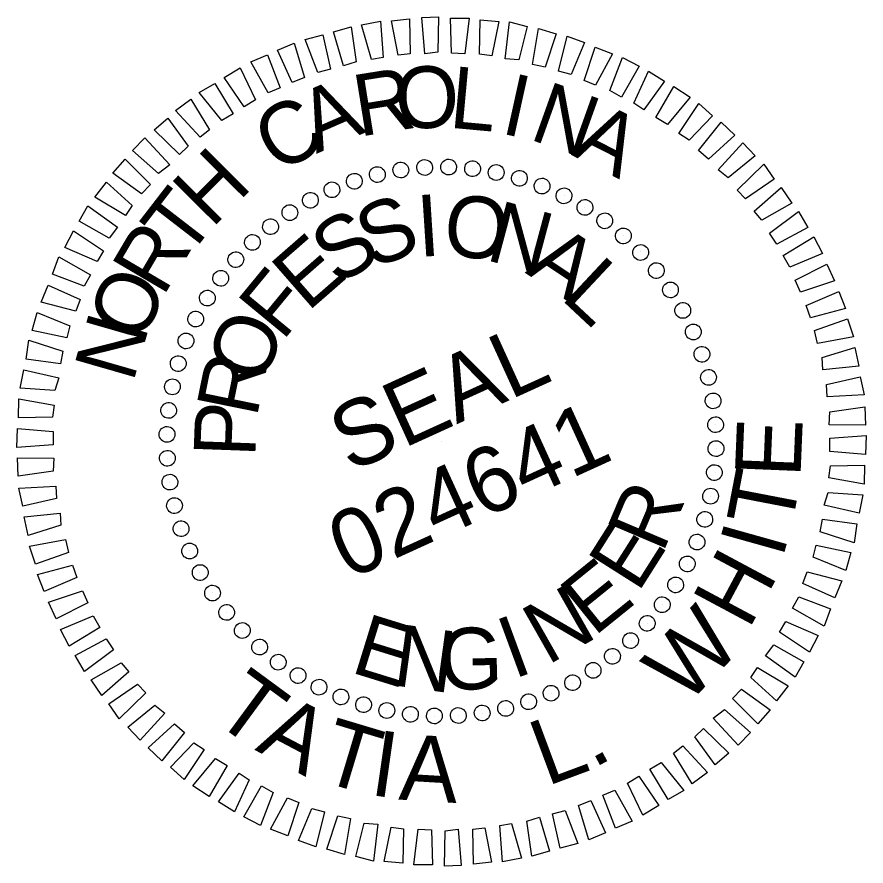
# Model space of a CAD drawing. Extents: x 2246788 to 2248774, y 662010 to 663780.
# Drawn here: x 2248546.8 to 2248624.4, y 663661 to 663738.6 of the extents above; entities that cross this region are included whole.
import ezdxf

# ---------------------------------------------------------------- set-up
doc = ezdxf.new("R2010")
doc.units = 0
doc.layers.add('Sheet Professional Seal CELL', color=7, linetype='Continuous')

msp = doc.modelspace()

# ---------------------------------------------------------------- linework, layer by layer
at = {"layer": 'Sheet Professional Seal CELL'}
for p, q in [((2248584.056, 663724.9), (2248584.056, 663724.9)), ((2248586.249, 663724.911), (2248586.249, 663724.911)), ((2248588.438, 663724.81), (2248588.438, 663724.81)), ((2248579.757, 663724.203), (2248579.757, 663724.203)), ((2248581.855, 663724.665), (2248581.855, 663724.665)), ((2248590.594, 663724.419), (2248590.594, 663724.419)), ((2248577.656, 663723.63), (2248577.656, 663723.63)), ((2248592.747, 663723.917), (2248592.747, 663723.917)), ((2248594.779, 663723.195), (2248594.779, 663723.195)), ((2248575.592, 663722.854), (2248575.592, 663722.854)), ((2248573.611, 663721.895), (2248573.611, 663721.895)), ((2248596.829, 663722.316), (2248596.829, 663722.316)), ((2248598.692, 663721.243), (2248598.692, 663721.243)), ((2248571.779, 663720.73), (2248571.779, 663720.73)), ((2248569.943, 663719.454), (2248569.943, 663719.454)), ((2248600.527, 663719.991), (2248600.527, 663719.991)), ((2248602.246, 663718.632), (2248602.246, 663718.632)), ((2248568.281, 663718.037), (2248568.281, 663718.037)), ((2248603.803, 663717.144), (2248603.803, 663717.144)), ((2248566.794, 663716.479), (2248566.794, 663716.479)), ((2248605.221, 663715.482), (2248605.221, 663715.482)), ((2248565.434, 663714.76), (2248565.434, 663714.76)), ((2248606.497, 663713.646), (2248606.497, 663713.646)), ((2248564.183, 663712.925), (2248564.183, 663712.925)), ((2248607.662, 663711.814), (2248607.662, 663711.814)), ((2248563.109, 663711.062), (2248563.109, 663711.062)), ((2248608.62, 663709.833), (2248608.62, 663709.833)), ((2248562.23, 663709.013), (2248562.23, 663709.013)), ((2248609.397, 663707.769), (2248609.397, 663707.769)), ((2248561.508, 663706.98), (2248561.508, 663706.98)), ((2248609.97, 663705.668), (2248609.97, 663705.668)), ((2248561.006, 663704.828), (2248561.006, 663704.828)), ((2248610.432, 663703.571), (2248610.432, 663703.571)), ((2248560.615, 663702.671), (2248560.615, 663702.671)), ((2248610.666, 663701.369), (2248610.666, 663701.369)), ((2248560.515, 663700.482), (2248560.515, 663700.482)), ((2248585.596, 663699.829), (2248585.596, 663699.829)), ((2248610.677, 663699.176), (2248610.677, 663699.176)), ((2248560.525, 663698.289), (2248560.525, 663698.289)), ((2248610.577, 663696.987), (2248610.577, 663696.987)), ((2248560.76, 663696.088), (2248560.76, 663696.088)), ((2248610.186, 663694.831), (2248610.186, 663694.831)), ((2248561.222, 663693.99), (2248561.222, 663693.99)), ((2248609.684, 663692.678), (2248609.684, 663692.678)), ((2248561.795, 663691.889), (2248561.795, 663691.889)), ((2248608.962, 663690.646), (2248608.962, 663690.646)), ((2248562.571, 663689.825), (2248562.571, 663689.825)), ((2248608.083, 663688.596), (2248608.083, 663688.596)), ((2248563.53, 663687.844), (2248563.53, 663687.844)), ((2248607.009, 663686.733), (2248607.009, 663686.733)), ((2248564.695, 663686.012), (2248564.695, 663686.012)), ((2248605.758, 663684.898), (2248605.758, 663684.898)), ((2248565.971, 663684.176), (2248565.971, 663684.176)), ((2248604.398, 663683.179), (2248604.398, 663683.179)), ((2248567.389, 663682.515), (2248567.389, 663682.515)), ((2248602.911, 663681.622), (2248602.911, 663681.622)), ((2248568.946, 663681.027), (2248568.946, 663681.027)), ((2248601.249, 663680.205), (2248601.249, 663680.205)), ((2248570.665, 663679.667), (2248570.665, 663679.667)), ((2248572.5, 663678.416), (2248572.5, 663678.416)), ((2248599.413, 663678.928), (2248599.413, 663678.928)), ((2248597.581, 663677.763), (2248597.581, 663677.763)), ((2248574.363, 663677.342), (2248574.363, 663677.342)), ((2248595.6, 663676.805), (2248595.6, 663676.805)), ((2248576.413, 663676.463), (2248576.413, 663676.463)), ((2248593.536, 663676.028), (2248593.536, 663676.028)), ((2248578.445, 663675.741), (2248578.445, 663675.741)), ((2248580.598, 663675.239), (2248580.598, 663675.239)), ((2248591.435, 663675.455), (2248591.435, 663675.455)), ((2248582.754, 663674.849), (2248582.754, 663674.849)), ((2248584.943, 663674.748), (2248584.943, 663674.748)), ((2248587.136, 663674.759), (2248587.136, 663674.759)), ((2248589.337, 663674.993), (2248589.337, 663674.993))]:
    msp.add_line(p, q, dxfattribs=at)
for points in [[(2248579.194, 663734.718), (2248578.301, 663737.882), (2248580.013, 663738.223), (2248580.253, 663734.926)], [(2248581.648, 663735.122), (2248581.044, 663738.254), (2248582.662, 663738.442), (2248582.748, 663735.239)], [(2248584.068, 663735.236), (2248583.808, 663738.58), (2248585.33, 663738.615), (2248585.26, 663735.395)], [(2248586.51, 663735.306), (2248586.423, 663738.508), (2248588.124, 663738.514), (2248587.739, 663735.262)], [(2248589.079, 663735.213), (2248589.125, 663738.367), (2248590.843, 663738.216), (2248590.193, 663735.062)], [(2248591.414, 663734.794), (2248591.803, 663738.159), (2248593.421, 663737.743), (2248592.664, 663734.705)], [(2248576.646, 663734.16), (2248575.728, 663737.258), (2248577.333, 663737.715), (2248577.8, 663734.521)], [(2248593.901, 663734.28), (2248594.444, 663737.55), (2248596.083, 663737.088), (2248595.056, 663734.037)], [(2248574.296, 663733.528), (2248573.13, 663736.568), (2248574.756, 663736.98), (2248575.471, 663733.844)], [(2248596.273, 663733.658), (2248597.06, 663736.874), (2248598.649, 663736.28), (2248597.449, 663733.37)], [(2248571.959, 663732.627), (2248570.611, 663735.585), (2248572.133, 663736.224), (2248573.072, 663733.08)], [(2248598.637, 663732.812), (2248599.618, 663735.843), (2248601.208, 663735.249), (2248599.651, 663732.396)], [(2248569.755, 663731.677), (2248568.179, 663734.531), (2248569.701, 663735.17), (2248570.867, 663732.13)], [(2248600.976, 663731.901), (2248602.135, 663734.902), (2248603.651, 663734.109), (2248602.028, 663731.281)], [(2248567.584, 663730.413), (2248565.756, 663733.096), (2248567.22, 663733.983), (2248568.613, 663731.047)], [(2248603.15, 663730.749), (2248604.508, 663733.676), (2248605.974, 663732.751), (2248604.09, 663730.133)], [(2248565.525, 663729.144), (2248563.469, 663731.724), (2248564.908, 663732.545), (2248566.554, 663729.778)], [(2248605.183, 663729.423), (2248606.806, 663732.251), (2248608.293, 663731.28), (2248606.235, 663728.803)], [(2248563.569, 663727.648), (2248561.307, 663730.078), (2248562.708, 663731.102), (2248564.421, 663728.311)], [(2248607.279, 663727.96), (2248609.1, 663730.714), (2248610.335, 663729.574), (2248608.219, 663727.345)], [(2248561.655, 663726.061), (2248559.364, 663728.313), (2248560.588, 663729.366), (2248562.465, 663726.815)], [(2248609.081, 663726.419), (2248611.142, 663729.008), (2248612.398, 663727.822), (2248609.992, 663725.626)], [(2248559.758, 663724.316), (2248557.372, 663726.415), (2248558.488, 663727.584), (2248560.771, 663725.108)], [(2248610.875, 663724.654), (2248613.11, 663727.103), (2248614.254, 663725.92), (2248611.765, 663723.906)], [(2248558.192, 663722.448), (2248555.574, 663724.332), (2248556.694, 663725.612), (2248559.006, 663723.314)], [(2248612.598, 663722.803), (2248615.033, 663725.177), (2248615.99, 663723.8), (2248613.352, 663721.992)], [(2248556.733, 663720.464), (2248553.93, 663722.153), (2248555.008, 663723.524), (2248557.349, 663721.404)], [(2248614.14, 663720.868), (2248616.612, 663723.039), (2248617.59, 663721.617), (2248614.848, 663720.037)], [(2248555.25, 663718.414), (2248552.509, 663719.967), (2248553.298, 663721.37), (2248556.002, 663719.416)], [(2248615.545, 663718.871), (2248618.212, 663720.856), (2248619.053, 663719.372), (2248616.225, 663717.862)], [(2248554.144, 663716.261), (2248551.192, 663717.553), (2248551.985, 663719.068), (2248554.739, 663717.247)], [(2248616.814, 663716.812), (2248619.605, 663718.524), (2248620.401, 663717.019), (2248617.403, 663715.761)], [(2248552.967, 663714.021), (2248550.053, 663715.11), (2248550.647, 663716.7), (2248553.541, 663715.052)], [(2248617.896, 663714.558), (2248620.791, 663716.043), (2248621.497, 663714.496), (2248618.394, 663713.466)], [(2248552.192, 663711.744), (2248549.021, 663712.551), (2248549.681, 663714.116), (2248552.588, 663712.804)], [(2248618.888, 663712.262), (2248621.887, 663713.52), (2248622.48, 663711.977), (2248619.295, 663711.129)], [(2248551.388, 663709.289), (2248548.213, 663709.985), (2248548.675, 663711.624), (2248551.651, 663710.399)], [(2248619.656, 663709.975), (2248622.692, 663711.029), (2248623.216, 663709.4), (2248619.927, 663708.779)], [(2248550.811, 663706.938), (2248547.649, 663707.365), (2248547.912, 663709.078), (2248551.009, 663708.072)], [(2248620.35, 663707.489), (2248623.337, 663708.411), (2248623.724, 663706.719), (2248620.422, 663706.367)], [(2248550.276, 663704.496), (2248547.106, 663704.699), (2248547.435, 663706.388), (2248550.631, 663705.647)], [(2248620.755, 663705.035), (2248623.845, 663705.73), (2248624.211, 663704.084), (2248620.826, 663703.914)], [(2248550.077, 663702.042), (2248546.965, 663701.997), (2248547.004, 663703.718), (2248550.228, 663703.155)], [(2248621.068, 663702.54), (2248624.262, 663703.008), (2248624.314, 663701.328), (2248621.003, 663701.357)], [(2248550.121, 663699.534), (2248546.823, 663699.295), (2248546.863, 663701.016), (2248550.12, 663700.743)], [(2248621.071, 663700.124), (2248624.369, 663700.364), (2248624.329, 663698.642), (2248621.072, 663698.916)], [(2248550.124, 663697.118), (2248546.93, 663696.651), (2248546.878, 663698.331), (2248550.189, 663698.301)], [(2248621.115, 663697.616), (2248624.227, 663697.661), (2248624.188, 663695.94), (2248620.964, 663696.503)], [(2248550.437, 663694.623), (2248547.347, 663693.928), (2248546.981, 663695.575), (2248550.365, 663695.744)], [(2248620.915, 663695.162), (2248624.085, 663694.959), (2248623.756, 663693.27), (2248620.561, 663694.011)], [(2248550.841, 663692.17), (2248547.855, 663691.247), (2248547.468, 663692.939), (2248550.77, 663693.291)], [(2248620.38, 663692.72), (2248623.542, 663692.293), (2248623.28, 663690.58), (2248620.183, 663691.586)], [(2248551.535, 663689.683), (2248548.499, 663688.629), (2248547.976, 663690.259), (2248551.265, 663690.879)], [(2248619.804, 663690.369), (2248622.979, 663689.673), (2248622.517, 663688.034), (2248619.54, 663689.26)], [(2248552.304, 663687.396), (2248549.305, 663686.139), (2248548.712, 663687.681), (2248551.897, 663688.529)], [(2248619, 663687.914), (2248622.171, 663687.107), (2248621.51, 663685.542), (2248618.604, 663686.854)], [(2248553.295, 663685.101), (2248550.401, 663683.616), (2248549.695, 663685.163), (2248552.798, 663686.192)], [(2248618.225, 663685.637), (2248621.139, 663684.548), (2248620.545, 663682.959), (2248617.651, 663684.606)], [(2248554.378, 663682.847), (2248551.587, 663681.134), (2248550.791, 663682.64), (2248553.789, 663683.897)], [(2248617.048, 663683.397), (2248620, 663682.106), (2248619.207, 663680.59), (2248616.453, 663682.412)], [(2248555.647, 663680.787), (2248552.98, 663678.802), (2248552.138, 663680.287), (2248554.967, 663681.796)], [(2248615.942, 663681.244), (2248618.683, 663679.692), (2248617.894, 663678.288), (2248615.19, 663680.242)], [(2248557.052, 663678.79), (2248554.58, 663676.619), (2248553.602, 663678.041), (2248556.343, 663679.621)], [(2248614.459, 663679.194), (2248617.262, 663677.505), (2248616.184, 663676.134), (2248613.843, 663678.254)], [(2248558.594, 663676.856), (2248556.159, 663674.482), (2248555.202, 663675.859), (2248557.84, 663677.666)], [(2248613, 663677.21), (2248615.618, 663675.326), (2248614.498, 663674.046), (2248612.186, 663676.344)], [(2248560.317, 663675.004), (2248558.082, 663672.556), (2248556.938, 663673.738), (2248559.427, 663675.752)], [(2248611.434, 663675.342), (2248613.82, 663673.243), (2248612.704, 663672.075), (2248610.421, 663674.551)], [(2248562.111, 663673.239), (2248560.049, 663670.65), (2248558.794, 663671.836), (2248561.2, 663674.033)], [(2248609.537, 663673.598), (2248611.828, 663671.345), (2248610.604, 663670.293), (2248608.727, 663672.844)], [(2248563.913, 663671.698), (2248562.092, 663668.944), (2248560.857, 663670.084), (2248562.973, 663672.313)], [(2248607.623, 663672.011), (2248609.885, 663669.58), (2248608.483, 663668.556), (2248606.771, 663671.347)], [(2248566.009, 663670.235), (2248564.386, 663667.407), (2248562.899, 663668.378), (2248564.957, 663670.855)], [(2248605.667, 663670.514), (2248607.723, 663667.935), (2248606.284, 663667.114), (2248604.638, 663669.88)], [(2248568.042, 663668.91), (2248566.684, 663665.982), (2248565.218, 663666.907), (2248567.102, 663669.525)], [(2248603.608, 663669.246), (2248605.436, 663666.562), (2248603.972, 663665.675), (2248602.578, 663668.611)], [(2248570.216, 663667.758), (2248569.057, 663664.756), (2248567.541, 663665.549), (2248569.164, 663668.377)], [(2248601.437, 663667.981), (2248603.013, 663665.128), (2248601.491, 663664.489), (2248600.324, 663667.529)], [(2248572.555, 663666.846), (2248571.574, 663663.816), (2248569.984, 663664.41), (2248571.541, 663667.263)], [(2248599.233, 663667.031), (2248600.581, 663664.074), (2248599.059, 663663.435), (2248598.12, 663666.578)], [(2248574.919, 663666), (2248574.132, 663662.784), (2248572.543, 663663.378), (2248573.743, 663666.289)], [(2248596.896, 663666.13), (2248598.062, 663663.09), (2248596.436, 663662.678), (2248595.721, 663665.814)], [(2248577.291, 663665.378), (2248576.748, 663662.109), (2248575.109, 663662.57), (2248576.136, 663665.621)], [(2248594.546, 663665.498), (2248595.464, 663662.4), (2248593.859, 663661.943), (2248593.392, 663665.137)], [(2248579.778, 663664.864), (2248579.389, 663661.499), (2248577.771, 663661.915), (2248578.528, 663664.954)], [(2248582.113, 663664.445), (2248582.067, 663661.292), (2248580.349, 663661.443), (2248580.999, 663664.597)], [(2248584.682, 663664.353), (2248584.769, 663661.15), (2248583.068, 663661.144), (2248583.453, 663664.397)], [(2248587.124, 663664.422), (2248587.384, 663661.079), (2248585.862, 663661.044), (2248585.932, 663664.263)], [(2248589.544, 663664.536), (2248590.148, 663661.405), (2248588.53, 663661.217), (2248588.444, 663664.419)], [(2248591.998, 663664.941), (2248592.891, 663661.776), (2248591.178, 663661.435), (2248590.939, 663664.733)]]:
    msp.add_lwpolyline(points, close=True, dxfattribs=at)
for centre, major_axis in [((2248584.06, 663724.862), (-0.044, 0.719)), ((2248586.247, 663724.901), (0.019, 0.72)), ((2248579.736, 663724.215), (-0.168, 0.7)), ((2248581.884, 663724.633), (-0.107, 0.712)), ((2248588.43, 663724.749), (0.081, 0.715)), ((2248590.591, 663724.407), (0.143, 0.706)), ((2248577.633, 663723.611), (-0.229, 0.683)), ((2248592.714, 663723.878), (0.204, 0.69)), ((2248594.783, 663723.166), (0.264, 0.67)), ((2248575.59, 663722.827), (-0.287, 0.66)), ((2248573.624, 663721.867), (-0.344, 0.633)), ((2248596.782, 663722.276), (0.321, 0.644)), ((2248598.696, 663721.216), (0.376, 0.614)), ((2248571.749, 663720.74), (-0.398, 0.6)), ((2248569.979, 663719.454), (-0.448, 0.563)), ((2248600.51, 663719.993), (0.428, 0.579)), ((2248602.21, 663718.616), (0.477, 0.539)), ((2248568.328, 663718.018), (-0.496, 0.522)), ((2248603.785, 663717.097), (0.522, 0.496)), ((2248566.809, 663716.444), (-0.539, 0.477)), ((2248605.22, 663715.446), (0.563, 0.448)), ((2248565.432, 663714.743), (-0.579, 0.428)), ((2248606.507, 663713.676), (0.6, 0.398)), ((2248564.209, 663712.929), (-0.614, 0.376)), ((2248607.634, 663711.801), (0.633, 0.344)), ((2248563.149, 663711.015), (-0.644, 0.321)), ((2248608.594, 663709.835), (0.66, 0.287)), ((2248562.259, 663709.016), (-0.67, 0.264)), ((2248609.378, 663707.792), (0.683, 0.229)), ((2248561.547, 663706.947), (-0.69, 0.204)), ((2248609.982, 663705.689), (0.7, 0.168)), ((2248561.018, 663704.824), (-0.706, 0.143)), ((2248610.4, 663703.541), (0.712, 0.107)), ((2248560.677, 663702.663), (-0.715, 0.081)), ((2248610.629, 663701.366), (0.719, 0.044)), ((2248560.524, 663700.48), (-0.72, 0.019)), ((2248610.668, 663699.178), (0.72, -0.019)), ((2248560.563, 663698.293), (-0.719, -0.044)), ((2248610.515, 663696.995), (0.715, -0.081)), ((2248560.792, 663696.117), (-0.712, -0.107)), ((2248610.174, 663694.834), (0.706, -0.143)), ((2248561.21, 663693.969), (-0.7, -0.168)), ((2248609.645, 663692.711), (0.69, -0.204)), ((2248561.814, 663691.866), (-0.683, -0.229)), ((2248608.933, 663690.642), (0.67, -0.264)), ((2248562.598, 663689.824), (-0.66, -0.287)), ((2248608.043, 663688.643), (0.644, -0.321)), ((2248563.558, 663687.857), (-0.633, -0.344)), ((2248606.983, 663686.729), (0.614, -0.376)), ((2248564.685, 663685.982), (-0.6, -0.398)), ((2248605.76, 663684.915), (0.579, -0.428)), ((2248565.971, 663684.212), (-0.563, -0.448)), ((2248604.383, 663683.215), (0.539, -0.477)), ((2248567.407, 663682.561), (-0.522, -0.496)), ((2248602.864, 663681.64), (0.496, -0.522)), ((2248568.981, 663681.042), (-0.477, -0.539)), ((2248601.213, 663680.205), (0.448, -0.563)), ((2248570.682, 663679.665), (-0.428, -0.579)), ((2248572.496, 663678.442), (-0.376, -0.614)), ((2248599.443, 663678.918), (0.398, -0.6)), ((2248574.41, 663677.382), (-0.321, -0.644)), ((2248597.568, 663677.791), (0.344, -0.633)), ((2248595.602, 663676.831), (0.287, -0.66)), ((2248576.409, 663676.492), (-0.264, -0.67)), ((2248593.559, 663676.047), (0.229, -0.683)), ((2248578.478, 663675.78), (-0.204, -0.69)), ((2248580.601, 663675.252), (-0.143, -0.706)), ((2248591.456, 663675.443), (0.168, -0.7)), ((2248582.762, 663674.91), (-0.081, -0.715)), ((2248584.945, 663674.758), (-0.019, -0.72)), ((2248587.132, 663674.796), (0.044, -0.719)), ((2248589.308, 663675.025), (0.107, -0.712))]:
    msp.add_ellipse(centre, major_axis=major_axis, ratio=0.999708, dxfattribs=at)

# ---------------------------------------------------------------- texts
for s, height, rotation, p in [('O', 5.638, 1.93343, (2248581.428, 663728.372)), ('L', 5.638, 354.73314, (2248586.199, 663728.515)), ('R', 5.638, 9.13336, (2248578.069, 663727.665)), ('I', 5.638, 347.5324, (2248590.88, 663728.011)), ('N', 5.639, 340.33117, (2248593.479, 663727.493)), ('A', 5.638, 23.53258, (2248574.164, 663726.104)), ('C', 5.638, 30.73213, (2248570.695, 663724.193)), ('A', 5.639, 333.12941, (2248597.387, 663726.033)), ('H', 5.638, 45.13174, (2248564.61, 663719.22)), ('T', 5.638, 52.33203, (2248562.337, 663716.37)), ('S', 5.638, 22.41266, (2248579.312, 663715.538)), ('I', 5.638, 3.70186, (2248583.515, 663716.685)), ('O', 5.638, 354.34574, (2248585.625, 663716.878)), ('N', 5.638, 344.98887, (2248589.503, 663716.448)), ('S', 5.638, 31.76787, (2248576.057, 663713.999)), ('R', 5.638, 59.53277, (2248560.156, 663712.958)), ('E', 5.638, 41.12333, (2248573.354, 663711.612)), ('A', 5.639, 326.27253, (2248593.175, 663715.265)), ('L', 5.639, 316.91311, (2248596.381, 663712.935)), ('F', 5.638, 50.47929, (2248571.065, 663708.92)), ('O', 5.638, 66.734, (2248558.303, 663708.706)), ('N', 5.639, 73.93576, (2248557.414, 663705.113)), ('O', 5.639, 69.1935, (2248569.286, 663704.866)), ('SEAL', 5.9982, 24.51226, (2248577.238, 663696.951)), ('R', 5.639, 78.55191, (2248568.71, 663701.911)), ('P', 5.639, 87.91115, (2248568.582, 663698.336)), ('024641', 5.9982, 24.51226, (2248577.116, 663687.161)), ('E', 5.998, 87.63115, (2248618.376, 663696.471)), ('T', 5.998, 79.10933, (2248617.516, 663691.651)), ('R', 5.639, 66.99367, (2248605.789, 663689.529)), ('E', 5.638, 57.63635, (2248603.534, 663685.918)), ('I', 5.998, 74.34486, (2248616.727, 663689.028)), ('H', 5.998, 61.83328, (2248613.647, 663682.54)), ('E', 5.638, 38.92402, (2248599.521, 663681.945)), ('N', 5.638, 29.56865, (2248595.266, 663679.345)), ('W', 5.998, 46.12601, (2248607.92, 663675.592)), ('E', 5.638, 342.78915, (2248577.167, 663678.785)), ('I', 5.638, 20.21346, (2248592.156, 663678.092)), ('N', 5.638, 352.14622, (2248581.017, 663677.573)), ('G', 5.638, 1.5025, (2248585.408, 663677.103)), ('T', 5.998, 323.6774, (2248564.503, 663674.514)), ('A', 5.998, 332.19922, (2248568.487, 663671.668)), ('T', 5.998, 343.27759, (2248574.217, 663668.905)), ('L', 5.998, 20.42498, (2248595.2, 663668.308)), ('I', 5.998, 351.79941, (2248578.925, 663667.56)), ('A', 5.998, 356.56388, (2248581.628, 663667.118)), ('.', 5.998, 28.28829, (2248599.422, 663669.919))]:
    msp.add_text(s, height=height, rotation=rotation, dxfattribs=at).set_placement(p)

doc.saveas('drawing.dxf')
